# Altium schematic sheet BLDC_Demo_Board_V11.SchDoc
size 322 x 223 mm; PageSetup: Record=PageOptions|CenterHorizontal=True|CenterVertical=True|PrintScale=0.88|XCorrection=1.00|YCorrection=1.00|PrintKind=0|BorderSize=5000000|LeftOffset=0|BottomOffset=0|Orientation=2|PaperLength=1000|PaperWidth=1000|Scale=100|PaperSource=7|PrintQuality=-4|MediaType=1|DitherType=10|PaperKind=A4 (210 x 297 mm)|PrintScaleMode=1
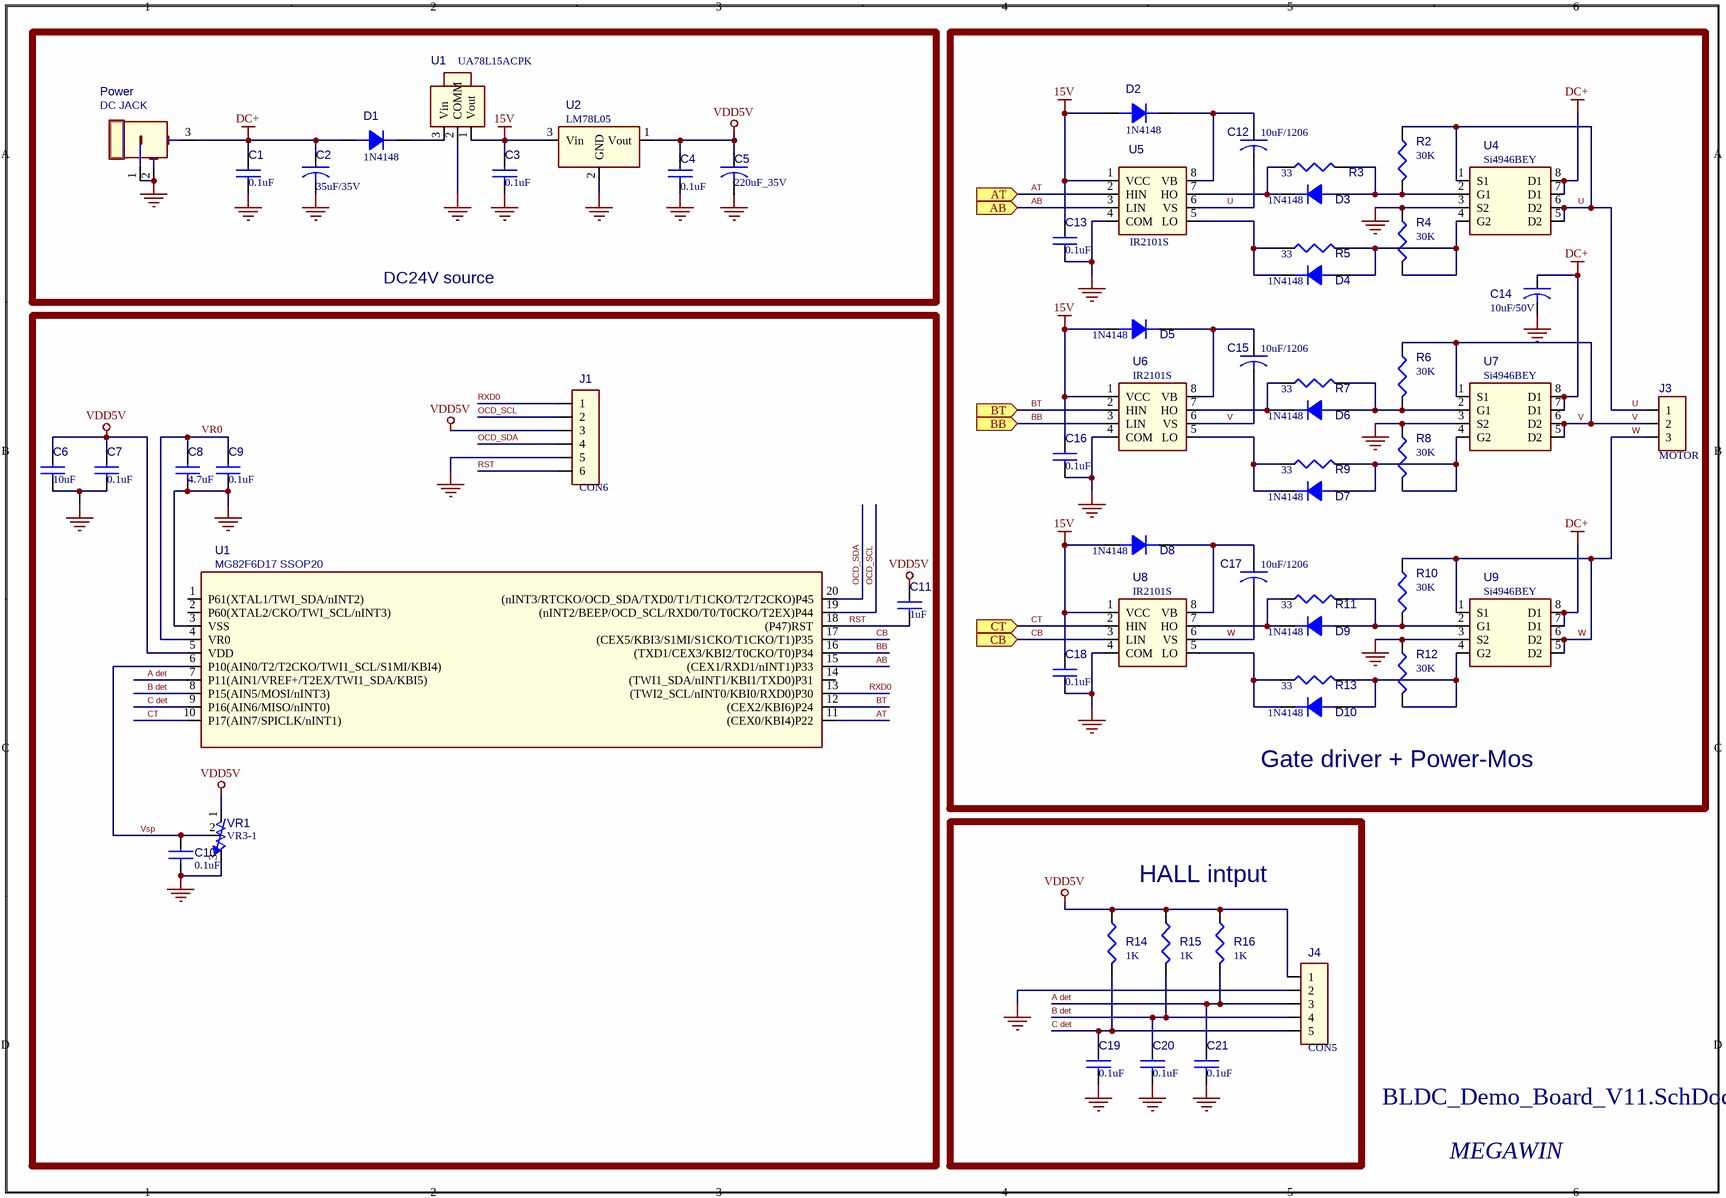
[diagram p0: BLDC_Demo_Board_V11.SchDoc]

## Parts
(Parts that share a designator on the sheet are numbered #1, #2 ... from top to bottom, then left to right.)
C1  0.1uF  [0603C]
C2  35uF/35V  [CEC060p025]
C3  0.1uF  [0603C]
C4  0.1uF  [0603C]
C5  220uF_35V  [CEC100p050]
C6  10uF  [0805C]
C7  0.1uF  [0603C]
C8  4.7uF  [0805C]
C9  0.1uF  [0603C]
C10  0.1uF  [0603C]
C11  1uF  [0603C]
C12  10uF/1206  [1206C]
C13  0.1uF  [0603C]
C14  10uF/50V  [CEC5X11P2]
C15  10uF/1206  [1206C]
C16  0.1uF  [0603C]
C17  10uF/1206  [1206C]
C18  0.1uF  [0603C]
C19  0.1uF  [0603C]
C20  0.1uF  [0603C]
C21  0.1uF  [0603C]
D1  1N4148  [D4148_SMD]
D2  1N4148  [D4148_SMD]
D3  1N4148  [D4148_SMD]
D4  1N4148  [D4148_SMD]
D5  1N4148  [D4148_SMD]
D6  1N4148  [D4148_SMD]
D7  1N4148  [D4148_SMD]
D8  1N4148  [D4148_SMD]
D9  1N4148  [D4148_SMD]
D10  1N4148  [D4148_SMD]
J1  CON6  [PS6P254]
J3  MOTOR  [PIN3_500_DT]
J4  CON5  [PIN5_500_DT]
MW1  MEGAWIN  [MEGAWIN_T]  (value not drawn)  (no BOM)
Power  DC JACK  [JACK_DC]
R2  30K  [0603R]
R3  33  [0603R]
R4  30K  [0603R]
R5  33  [0603R]
R6  30K  [0603R]
R7  33  [0603R]
R8  30K  [0603R]
R9  33  [0603R]
R10  30K  [0603R]
R11  33  [0603R]
R12  30K  [0603R]
R13  33  [0603R]
R14  1K  [0603R]
R15  1K  [0603R]
R16  1K  [0603R]
U1#1  UA78L15ACPK  [SOT89]
U1#2  MG82F6D17 SSOP20  [SOCK_SSOP28 _150P0635]
U2  LM78L05  [SOT89]
U4  Si4946BEY  [SO8_150P127]
U5  IR2101S  [SO8_150P127]
U6  IR2101S  [SO8_150P127]
U7  Si4946BEY  [SO8_150P127]
U8  IR2101S  [SO8_150P127]
U9  Si4946BEY  [SO8_150P127]
VR1  VR3-1  [VR9_90]

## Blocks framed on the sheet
DC24V source: C1-C5 D1 Power U1#1 U2
Gate driver + Power-Mos: C12-C18 D2-D10 J3 R2-R13 U4-U9
HALL intput: C19-C21 J4 R14-R16

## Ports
AB (in), AT (in), BB (in), BT (in), CB (in), CT (in)

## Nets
15V: C3.1 C13.1 C16.1 C18.1 D2.1(ANODE) D5.1(ANODE) D8.1(ANODE) U1#1.1(Vout) U2.3(Vin) U5.1(VCC) U6.1(VCC) U8.1(VCC)
DC+: C1.1 C2.1 C14.1 D1.1(ANODE) Power.3(DC+) U4.7(D1) U4.8(D1) U7.7(D1) U7.8(D1) U9.7(D1) U9.8(D1)
GND: C1.2 C2.2 C3.2 C4.2 C5.2 C6.2 C7.2 C8.2 C9.2 C10.2 C13.2 C14.2 C16.2 C18.2 C19.2 C20.2 C21.2 J1.5 J4.2 Power.1(DC-) Power.2(NA) R4.1 R8.1 R12.1 U1#1.2(COMM) U1#2.3(VSS) U2.2(GND) U4.3(S2) U5.4(COM) U6.4(COM) U7.3(S2) U8.4(COM) U9.3(S2) VR1.3
VDD5V: C4.1 C5.1 C6.1 C7.1 C11.1 J1.3 J4.1 R14.1 R15.1 R16.1 U1#2.5(VDD) U2.1(Vout) VR1.1
A det: C21.1 J4.3 R16.2 U1#2.7(P11(AIN1/VREF+/T2EX/TWI1_SDA/KBI5))
AB: U1#2.15((CEX1/RXD1/nINT1)P33) U5.3(LIN) ; port AB
AT: U1#2.11((CEX0/KBI4)P22) U5.2(HIN) ; port AT
B det: C20.1 J4.4 R15.2 U1#2.8(P15(AIN5/MOSI/nINT3))
BB: U1#2.16((TXD1/CEX3/KBI2/T0CKO/T0)P34) U6.3(LIN) ; port BB
BT: U1#2.12((CEX2/KBI6)P24) U6.2(HIN) ; port BT
C det: C19.1 J4.5 R14.2 U1#2.9(P16(AIN6/MISO/nINT0))
CB: U1#2.17((CEX5/KBI3/S1MI/S1CKO/T1CKO/T1)P35) U8.3(LIN) ; port CB
CT: U1#2.10(P17(AIN7/SPICLK/nINT1)) U8.2(HIN) ; port CT
OCD_SCL: J1.2 U1#2.19((nINT2/BEEP/OCD_SCL/RXD0/T0/T0CKO/T2EX)P44)
OCD_SDA: J1.4 U1#2.20((nINT3/RTCKO/OCD_SDA/TXD0/T1/T1CKO/T2/T2CKO)P45)
RST: C11.2 J1.6 U1#2.18((P47)RST)
RXD0: J1.1 U1#2.13((TWI2_SCL/nINT0/KBI0/RXD0)P30)
U: C12.2 J3.1 R2.1 U4.1(S1) U4.5(D2) U4.6(D2) U5.6(VS)
V: C15.2 J3.2 R6.1 U6.6(VS) U7.1(S1) U7.5(D2) U7.6(D2)
VR0: C8.1 C9.1 U1#2.4(VR0)
Vsp: C10.1 U1#2.6(P10(AIN0/T2/T2CKO/TWI1_SCL/S1MI/KBI4)) VR1.2(W)
W: C17.2 J3.3 R10.1 U8.6(VS) U9.1(S1) U9.5(D2) U9.6(D2)
NetC12_1: C12.1 D2.2(CATHODE) U5.8(VB)
NetC15_1: C15.1 D5.2(CATHODE) U6.8(VB)
NetC17_1: C17.1 D8.2(CATHODE) U8.8(VB)
NetD1_2: D1.2(CATHODE) U1#1.3(Vin)
NetD3_1: D3.1(ANODE) R2.2 R3.2 U4.2(G1)
NetD3_2: D3.2(CATHODE) R3.1 U5.7(HO)
NetD4_1: D4.1(ANODE) R4.2 R5.2 U4.4(G2)
NetD4_2: D4.2(CATHODE) R5.1 U5.5(LO)
NetD6_1: D6.1(ANODE) R6.2 R7.2 U7.2(G1)
NetD6_2: D6.2(CATHODE) R7.1 U6.7(HO)
NetD7_1: D7.1(ANODE) R8.2 R9.2 U7.4(G2)
NetD7_2: D7.2(CATHODE) R9.1 U6.5(LO)
NetD9_1: D9.1(ANODE) R10.2 R11.2 U9.2(G1)
NetD9_2: D9.2(CATHODE) R11.1 U8.7(HO)
NetD10_1: D10.1(ANODE) R12.2 R13.2 U9.4(G2)
NetD10_2: D10.2(CATHODE) R13.1 U8.5(LO)

Not connected (* = marked no-connect by the designer): U1#2 1(P61(XTAL1/TWI_SDA/nINT2)) 2(P60(XTAL2/CKO/TWI_SCL/nINT3)) 14((TWI1_SDA/nINT1/KBI1/TXD0)P31)

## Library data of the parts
C1 C3 C4 C8 C9 = CAP NP_Dup1
C2 C5 = CAP_Dup1
C6 C7 C10 C11 C13 C16 C18-C21 = CAP NP
C12 C14 C15 C17 = CAP
D1 D2 D5 D8 = ES1A/SM
J3 = CON3
R2 R4 R6 R8 R10 R12 = R
R3 R5 R7 R9 R11 R13-R16 = RESISTOR
U1#2 = MG82FG5B32_SOP20
U2 = AIC1734A_50PXT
